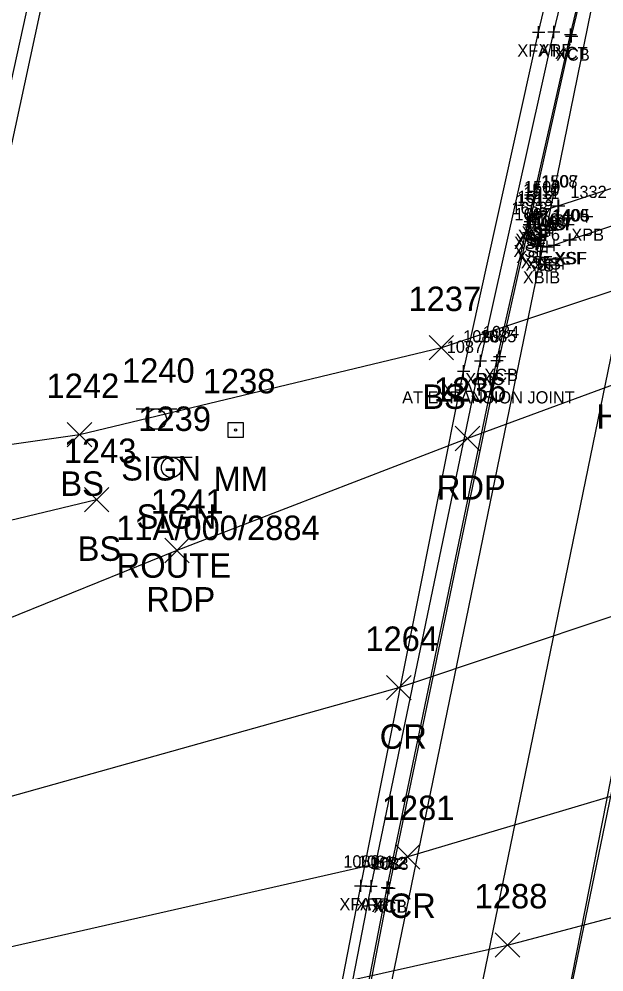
# Model space of a CAD drawing. Extents: x 1683147 to 1683637, y 416837 to 418211.
# Drawn here: x 1683280.1 to 1683328, y 417544.1 to 417622 of the extents above; entities that cross this region are included whole.
import ezdxf

# ---------------------------------------------------------------- set-up
doc = ezdxf.new("R2010")
doc.units = 0
for name, color, linetype in [('B_A', 7, 'Continuous'), ('B_C', 7, 'Continuous'), ('B_I', 7, 'Continuous'), ('B_TIC', 7, 'Continuous'), ('BB', 7, 'Continuous'), ('BDC', 7, 'Continuous'), ('BDEFAULT', 7, 'Continuous'), ('BELB', 7, 'Continuous'), ('BF', 7, 'Continuous'), ('BR', 7, 'Continuous'), ('C_A', 7, 'Continuous'), ('L_A', 7, 'Continuous'), ('L_I', 7, 'Continuous'), ('L_TIC', 7, 'Continuous'), ('LELB', 7, 'Continuous'), ('P_A', 7, 'Continuous'), ('P_I', 7, 'Continuous'), ('P_TIC', 7, 'Continuous'), ('PET', 7, 'Continuous'), ('PRC', 7, 'Continuous'), ('S_A', 7, 'Continuous'), ('S_C', 7, 'Continuous'), ('S_I', 7, 'Continuous'), ('SRM', 7, 'Continuous'), ('SSGN', 7, 'Continuous')]:
    doc.layers.add(name, color=color, linetype=linetype)

msp = doc.modelspace()

# ---------------------------------------------------------------- linework, layer by layer
at = {"layer": 'B_TIC'}
for p, q in [((1683322.673, 417620.925), (1683322.749, 417620.925)), ((1683323.917, 417620.951), (1683323.992, 417620.951)), ((1683325.28, 417620.725), (1683325.355, 417620.725)), ((1683325.373, 417620.597), (1683325.448, 417620.597)), ((1683324.264, 417606.736), (1683324.34, 417606.736)), ((1683324.316, 417606.736), (1683324.391, 417606.736)), ((1683322.508, 417606.053), (1683322.584, 417606.053)), ((1683322.863, 417606.265), (1683322.939, 417606.265)), ((1683321.899, 417605.207), (1683321.974, 417605.207)), ((1683322.001, 417605.46), (1683322.076, 417605.46)), ((1683322.195, 417605.787), (1683322.271, 417605.787)), ((1683326.611, 417605.87), (1683326.686, 417605.87)), ((1683321.844, 417604.539), (1683321.92, 417604.539)), ((1683321.844, 417604.539), (1683321.92, 417604.539)), ((1683322.083, 417604.05), (1683322.158, 417604.05)), ((1683322.458, 417603.617), (1683322.534, 417603.617)), ((1683325.193, 417603.951), (1683325.268, 417603.951)), ((1683325.266, 417603.957), (1683325.341, 417603.957)), ((1683322.841, 417603.436), (1683322.917, 417603.436)), ((1683323.376, 417603.37), (1683323.452, 417603.37)), ((1683323.946, 417603.519), (1683324.021, 417603.519)), ((1683322.815, 417602.383), (1683322.891, 417602.383)), ((1683319.49, 417594.409), (1683319.565, 417594.409)), ((1683317.913, 417594.057), (1683317.988, 417594.057)), ((1683319.263, 417594.072), (1683319.338, 417594.072)), ((1683316.534, 417593.209), (1683316.609, 417593.209)), ((1683308.116, 417551.126), (1683308.191, 417551.126)), ((1683308.971, 417551.101), (1683309.047, 417551.101)), ((1683310.277, 417550.995), (1683310.352, 417550.995)), ((1683310.434, 417550.936), (1683310.509, 417550.936))]:
    msp.add_line(p, q, dxfattribs=at)
for points in [[(1683322.17, 417620.925), (1683323.17, 417620.925)], [(1683322.67, 417620.425), (1683322.67, 417621.425)], [(1683323.413, 417620.951), (1683324.413, 417620.951)], [(1683323.913, 417620.451), (1683323.913, 417621.451)], [(1683324.776, 417620.725), (1683325.776, 417620.725)], [(1683325.276, 417620.225), (1683325.276, 417621.225)], [(1683325.369, 417620.097), (1683325.369, 417621.097)], [(1683324.869, 417620.597), (1683325.869, 417620.597)], [(1683322.86, 417605.765), (1683322.86, 417606.765)], [(1683323.761, 417606.736), (1683324.761, 417606.736)], [(1683323.812, 417606.736), (1683324.812, 417606.736)], [(1683324.261, 417606.236), (1683324.261, 417607.236)], [(1683324.312, 417606.236), (1683324.312, 417607.236)], [(1683321.997, 417604.96), (1683321.997, 417605.96)], [(1683322.005, 417606.053), (1683323.005, 417606.053)], [(1683322.192, 417605.287), (1683322.192, 417606.287)], [(1683322.36, 417606.265), (1683323.36, 417606.265)], [(1683322.505, 417605.553), (1683322.505, 417606.553)], [(1683326.607, 417605.37), (1683326.607, 417606.37)], [(1683321.395, 417605.207), (1683322.395, 417605.207)], [(1683321.497, 417605.46), (1683322.497, 417605.46)], [(1683321.692, 417605.787), (1683322.692, 417605.787)], [(1683321.895, 417604.707), (1683321.895, 417605.707)], [(1683326.107, 417605.87), (1683327.107, 417605.87)], [(1683321.341, 417604.539), (1683322.341, 417604.539)], [(1683321.341, 417604.539), (1683322.341, 417604.539)], [(1683321.841, 417604.039), (1683321.841, 417605.039)], [(1683321.841, 417604.039), (1683321.841, 417605.039)], [(1683322.079, 417603.55), (1683322.079, 417604.55)], [(1683325.189, 417603.451), (1683325.189, 417604.451)], [(1683325.262, 417603.457), (1683325.262, 417604.457)], [(1683321.579, 417604.05), (1683322.579, 417604.05)], [(1683321.955, 417603.617), (1683322.955, 417603.617)], [(1683322.455, 417603.117), (1683322.455, 417604.117)], [(1683322.838, 417602.936), (1683322.838, 417603.936)], [(1683323.373, 417602.87), (1683323.373, 417603.87)], [(1683323.942, 417603.019), (1683323.942, 417604.019)], [(1683324.689, 417603.951), (1683325.689, 417603.951)], [(1683324.762, 417603.957), (1683325.762, 417603.957)], [(1683322.338, 417603.436), (1683323.338, 417603.436)], [(1683322.812, 417601.883), (1683322.812, 417602.883)], [(1683322.873, 417603.37), (1683323.873, 417603.37)], [(1683323.442, 417603.519), (1683324.442, 417603.519)], [(1683322.312, 417602.383), (1683323.312, 417602.383)], [(1683317.909, 417593.557), (1683317.909, 417594.557)], [(1683318.986, 417594.409), (1683319.986, 417594.409)], [(1683319.259, 417593.572), (1683319.259, 417594.572)], [(1683319.486, 417593.909), (1683319.486, 417594.909)], [(1683316.53, 417592.709), (1683316.53, 417593.709)], [(1683317.409, 417594.057), (1683318.409, 417594.057)], [(1683318.759, 417594.072), (1683319.759, 417594.072)], [(1683316.03, 417593.209), (1683317.03, 417593.209)], [(1683308.112, 417550.626), (1683308.112, 417551.626)], [(1683308.968, 417550.601), (1683308.968, 417551.601)], [(1683310.273, 417550.495), (1683310.273, 417551.495)], [(1683310.43, 417550.436), (1683310.43, 417551.436)], [(1683307.612, 417551.126), (1683308.612, 417551.126)], [(1683308.468, 417551.101), (1683309.468, 417551.101)], [(1683309.773, 417550.995), (1683310.773, 417550.995)], [(1683309.93, 417550.936), (1683310.93, 417550.936)]]:
    msp.add_lwpolyline(points, dxfattribs=at)
at = {"layer": 'BB'}
for points in [[(1683309.186, 417464.354), (1683321.096, 417522.255), (1683338.804, 417607.952), (1683349.063, 417657.849)], [(1683301.278, 417461.805), (1683313.213, 417519.604), (1683330.806, 417605.15), (1683341.02, 417655.206)], [(1683293.295, 417459.142), (1683305.221, 417516.944), (1683322.812, 417602.383), (1683333.052, 417652.523)]]:
    msp.add_lwpolyline(points, dxfattribs=at)
at = {"layer": 'BDC'}
for points in [[(1683293.283, 417456.91), (1683297.758, 417483.397), (1683303.439, 417515.718), (1683310.273, 417550.995), (1683319.259, 417594.072), (1683325.276, 417620.725), (1683333.387, 417654.646)], [(1683293.606, 417457.004), (1683297.933, 417483.396), (1683303.651, 417515.782), (1683310.43, 417550.936), (1683319.486, 417594.409), (1683325.369, 417620.597), (1683333.615, 417654.761)]]:
    msp.add_lwpolyline(points, dxfattribs=at)
at = {"layer": 'BDEFAULT'}
for points in [[(1683329.392, 417608.394), (1683324.312, 417606.736), (1683324.261, 417606.736), (1683322.86, 417606.265), (1683322.505, 417606.053), (1683322.192, 417605.787), (1683321.997, 417605.46), (1683321.895, 417605.207), (1683321.841, 417604.539)], [(1683330.297, 417605.624), (1683325.262, 417603.957), (1683325.189, 417603.951), (1683323.942, 417603.519), (1683323.373, 417603.37), (1683322.838, 417603.436), (1683322.455, 417603.617), (1683322.079, 417604.05), (1683321.841, 417604.539)]]:
    msp.add_lwpolyline(points, dxfattribs=at)
at = {"layer": 'BELB'}
msp.add_lwpolyline([(1683351.52, 417660.937), (1683344.246, 417631.627), (1683337.363, 417600.891), (1683329.97, 417566.982), (1683324.712, 417540.29), (1683321.043, 417521.799), (1683314.399, 417485.977), (1683310.141, 417462.954)], dxfattribs=at)
at = {"layer": 'BF'}
for points in [[(1683290.891, 417457.431), (1683295.203, 417483.369), (1683301.096, 417515.048), (1683308.112, 417551.126), (1683316.53, 417593.209), (1683322.67, 417620.925), (1683330.916, 417655.559)], [(1683250.624, 417454.9), (1683256.47, 417491.459), (1683260.265, 417514.98), (1683268.347, 417558.692), (1683275.679, 417593.916), (1683283.544, 417630.285), (1683288.924, 417653.565)]]:
    msp.add_lwpolyline(points, dxfattribs=at)
at = {"layer": 'BR'}
for points in [[(1683248.519, 417448.641), (1683249.479, 417455.186), (1683255.278, 417491.444), (1683259.237, 417514.807), (1683267.406, 417559.099), (1683274.406, 417593.753), (1683282.508, 417630.53), (1683290.526, 417665.488)], [(1683290.803, 417448.811), (1683292.09, 417457.121), (1683296.401, 417483.47), (1683301.973, 417515.177), (1683308.968, 417551.101), (1683317.909, 417594.057), (1683323.913, 417620.951), (1683332.125, 417655.111), (1683334.513, 417664.825)]]:
    msp.add_lwpolyline(points, dxfattribs=at)
at = {"layer": 'L_TIC'}
for points in [[(1683313.708, 417594.125), (1683315.708, 417596.125)], [(1683315.708, 417594.125), (1683313.708, 417596.125)], [(1683284.091, 417587.015), (1683286.091, 417589.015)], [(1683286.091, 417587.015), (1683284.091, 417589.015)], [(1683284.091, 417587.015), (1683286.091, 417589.015)], [(1683286.091, 417587.015), (1683284.091, 417589.015)], [(1683285.499, 417581.7), (1683287.499, 417583.7)], [(1683287.499, 417581.7), (1683285.499, 417583.7)]]:
    msp.add_lwpolyline(points, dxfattribs=at)
at = {"layer": 'LELB'}
for points in [[(1683441.899, 417645.225), (1683433.836, 417640.845), (1683426.438, 417636.464), (1683410.457, 417628.612), (1683364.366, 417611.634), (1683314.708, 417595.125), (1683285.091, 417588.015)], [(1683285.091, 417588.015), (1683258.675, 417584.256), (1683207.806, 417580.406)], [(1683286.499, 417582.7), (1683258.094, 417575.88), (1683207.744, 417572.779)]]:
    msp.add_lwpolyline(points, dxfattribs=at)
at = {"layer": 'P_TIC'}
for points in [[(1683315.848, 417586.705), (1683317.848, 417588.705)], [(1683317.848, 417586.705), (1683315.848, 417588.705)], [(1683292.07, 417577.551), (1683294.07, 417579.551)], [(1683294.07, 417577.551), (1683292.07, 417579.551)], [(1683310.228, 417566.333), (1683312.228, 417568.333)], [(1683312.228, 417566.333), (1683310.228, 417568.333)], [(1683310.955, 417552.502), (1683312.955, 417554.502)], [(1683312.955, 417552.502), (1683310.955, 417554.502)], [(1683319.124, 417545.282), (1683321.124, 417547.282)], [(1683321.124, 417545.282), (1683319.124, 417547.282)]]:
    msp.add_lwpolyline(points, dxfattribs=at)
at = {"layer": 'PET'}
msp.add_lwpolyline([(1683444.524, 417639.397), (1683404.458, 417622.242), (1683363.803, 417604.981), (1683316.848, 417587.705), (1683293.07, 417578.551), (1683271.475, 417569.828), (1683261.715, 417567.454), (1683241.63, 417563.083), (1683221.134, 417560.361), (1683207.789, 417560.65)], dxfattribs=at)
at = {"layer": 'PRC'}
for points in [[(1683206.154, 417544.862), (1683241.64, 417550.402), (1683274.909, 417557.18), (1683311.228, 417567.333), (1683337.826, 417576.227), (1683364.361, 417586.18)], [(1683342.592, 417562.589), (1683311.955, 417553.502), (1683276.156, 417545.385), (1683245.179, 417538.35), (1683203.393, 417531.667)], [(1683202.452, 417523.569), (1683242.343, 417529.845), (1683281.666, 417537.682), (1683320.124, 417546.282), (1683360.503, 417556.965)]]:
    msp.add_lwpolyline(points, dxfattribs=at)
at = {"layer": 'SRM'}
msp.add_lwpolyline([(1683297.248, 417589.025), (1683298.498, 417589.025), (1683298.498, 417587.775), (1683297.248, 417587.775)], close=True, dxfattribs=at)
msp.add_circle((1683297.873, 417588.4), 0.0833, dxfattribs=at)
at = {"layer": 'SSGN'}
for p, q in [((1683289.724, 417590.121), (1683293.058, 417590.121)), ((1683291.371, 417589.288), (1683291.371, 417589.288)), ((1683290.979, 417586.174), (1683294.312, 417586.174)), ((1683292.626, 417585.341), (1683292.626, 417585.341))]:
    msp.add_line(p, q, dxfattribs=at)
for centre in [(1683291.371, 417589.288), (1683292.626, 417585.341)]:
    msp.add_circle(centre, 0.833, dxfattribs=at)

# ---------------------------------------------------------------- texts
at = {"layer": 'B_A'}
for s, p in [('XFAT', (1683320.926, 417618.925)), ('XRF', (1683322.673, 417618.951)), ('XCT', (1683323.997, 417618.725)), ('XCB', (1683324.105, 417618.597)), ('XSF', (1683321.62, 417604.265)), ('XSF', (1683323.021, 417604.736)), ('XSF', (1683323.072, 417604.736)), ('XSF', (1683320.757, 417603.46)), ('XSF', (1683320.952, 417603.787)), ('XSF', (1683321.265, 417604.053)), ('XPB', (1683325.343, 417603.87)), ('XSF', (1683320.655, 417603.207)), ('XSF', (1683320.601, 417602.539)), ('XSF', (1683320.601, 417602.539)), ('XSF', (1683320.839, 417602.05)), ('XSF', (1683323.949, 417601.951)), ('XSF', (1683324.022, 417601.957)), ('XSF', (1683321.214, 417601.617)), ('XSF', (1683321.598, 417601.436)), ('XSF', (1683322.133, 417601.37)), ('XSF', (1683322.702, 417601.519)), ('XBIB', (1683321.383, 417600.383)), ('XRF', (1683316.669, 417592.057)), ('XCT', (1683317.98, 417592.072)), ('XCB', (1683318.223, 417592.409)), ('XFAT', (1683314.786, 417591.209)), ('XFAT', (1683306.368, 417549.126)), ('XRF', (1683307.728, 417549.101)), ('XCT', (1683308.994, 417548.995)), ('XCB', (1683309.167, 417548.936))]:
    msp.add_text(s, height=1, dxfattribs=at).set_placement(p)
at = {"layer": 'B_C'}
msp.add_text('AT EXPANSION JOINT', height=1, dxfattribs=at).set_placement((1683311.5, 417590.572))
at = {"layer": 'B_I'}
for s, p in [('1508', (1683322.875, 417608.236)), ('1507', (1683322.926, 417608.236)), ('1510', (1683321.399, 417607.553)), ('1511', (1683321.412, 417607.287)), ('1509', (1683321.47, 417607.765)), ('1332', (1683325.261, 417607.37)), ('1513', (1683320.832, 417606.707)), ('1512', (1683320.935, 417606.96)), ('1668', (1683320.447, 417606.039)), ('1668', (1683320.447, 417606.039)), ('1667', (1683320.686, 417605.55)), ('1410', (1683321.348, 417605.117)), ('1409', (1683321.448, 417604.936)), ('1407', (1683322.557, 417605.019)), ('1406', (1683323.776, 417605.451)), ('1405', (1683323.876, 417605.457)), ('1408', (1683321.987, 417604.87)), ('1376', (1683321.438, 417603.883)), ('1086', (1683316.496, 417595.557)), ('1085', (1683317.874, 417595.572)), ('1084', (1683318.101, 417595.909)), ('1087', (1683315.145, 417594.709)), ('1080', (1683306.683, 417552.626)), ('1081', (1683307.866, 417552.601)), ('1082', (1683308.888, 417552.495)), ('1083', (1683309.045, 417552.436))]:
    msp.add_text(s, height=1, dxfattribs=at).set_placement(p)
at = {"layer": 'C_A'}
msp.add_text('HVCTRL', height=2, dxfattribs=at).set_placement((1683327.401, 417588.507))
at = {"layer": 'L_A'}
for p in [(1683313.149, 417590.125), (1683283.532, 417583.015), (1683283.532, 417583.015), (1683284.94, 417577.7)]:
    msp.add_text('BS', height=2, dxfattribs=at).set_placement(p)
at = {"layer": 'L_I'}
for s, p in [('1237', (1683312.015, 417598.125)), ('1242', (1683282.398, 417591.015)), ('1242', (1683282.398, 417591.015)), ('1243', (1683283.806, 417585.7))]:
    msp.add_text(s, height=2, dxfattribs=at).set_placement(p)
at = {"layer": 'P_A'}
for s, p in [('RDP', (1683314.336, 417582.705)), ('RDP', (1683290.558, 417573.551)), ('CR', (1683309.661, 417562.333)), ('CR', (1683310.388, 417548.502))]:
    msp.add_text(s, height=2, dxfattribs=at).set_placement(p)
at = {"layer": 'P_I'}
for s, p in [('1236', (1683314.1, 417590.705)), ('1241', (1683290.945, 417581.551)), ('1264', (1683308.488, 417570.333)), ('1281', (1683309.829, 417556.502)), ('1288', (1683317.431, 417549.282))]:
    msp.add_text(s, height=2, dxfattribs=at).set_placement(p)
at = {"layer": 'S_A'}
for s, p in [('SIGN', (1683288.509, 417584.268)), ('MM', (1683296.062, 417583.4)), ('SIGN', (1683289.764, 417580.32))]:
    msp.add_text(s, height=2, dxfattribs=at).set_placement(p)
at = {"layer": 'S_C'}
for s, p in [('11A/000/2884', (1683288.094, 417579.4)), ('ROUTE', (1683288.134, 417576.32))]:
    msp.add_text(s, height=2, dxfattribs=at).set_placement(p)
at = {"layer": 'S_I'}
for s, p in [('1240', (1683288.572, 417592.268)), ('1238', (1683295.181, 417591.4)), ('1239', (1683289.905, 417588.32))]:
    msp.add_text(s, height=2, dxfattribs=at).set_placement(p)

doc.saveas('drawing.dxf')
